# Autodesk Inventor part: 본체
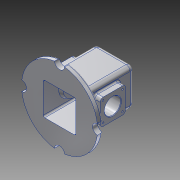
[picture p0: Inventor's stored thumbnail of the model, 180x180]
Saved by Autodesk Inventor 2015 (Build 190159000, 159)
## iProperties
Created: 2018-07
Part Number: 본체
Material: 알루미늄 6061
Document SubType Name: Modeling
Designer: pc
Density: 2.7 g/cm^3
Appearance: 알루미늄 - 평지
Mass: 909.432 g
Surface Area: 1017.53 cm^2
Volume: 336.827 cm^3
Author: pc
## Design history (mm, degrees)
sketch "스케치1"
  geometry: A1 r 10 centre (75, 0) between (74.333, 9.978) and (74.333, -9.978); A2 r 10 centre (0, -75) between (9.978, -74.333) and (-9.978, -74.333); A3 r 10 centre (0, 75) between (-9.978, 74.333) and (9.978, 74.333); A4 r 10 centre (-75, 0) between (-74.333, -9.978) and (-74.333, 9.978); A5 r 75 centre (0, 0) between (9.978, -74.333) and (74.333, -9.978); A6 r 75 centre (0, 0) between (74.333, 9.978) and (9.978, 74.333); A7 r 75 centre (0, 0) between (-9.978, 74.333) and (-74.333, 9.978); A8 r 75 centre (0, 0) between (-74.333, -9.978) and (-9.978, -74.333); 5 further points
  constraints: 16 point on circle, 8 centre point, 5 coincident, 2 horizontal alignment, 2 vertical alignment
  dimensions: "d1" = 20 diameter of A1; "d2" = 20 diameter of A2; "d3" = 20 diameter of A3; "d4" = 20 diameter of A4; "d5" = 75 radius of A5; "d6" = 75 radius of A6; "d7" = 75 radius of A7; "d8" = 75 radius of A8; "d9" = 150 distance of point (75, 0) point (-75, 0); "d10" = 150 distance of point (0, 75) point (0, -75); "d11" = 75 distance of point (0, 0) point (75, 0); "d12" = 75 distance of point (0, -75) point (0, 0)
extrude "돌출1" new body sketch "스케치1" distance "d13" = 10; taper "d14" = 0 deg
sketch "스케치2"
  geometry: L1 (-37, -37)-(37, -37); L2 (37, -37)-(37, 37); L3 (37, 37)-(-37, 37); L4 (-37, 37)-(-37, -37); L5 (0, -37)-(0, 37); L6 (37, 0)-(-37, 0); 2 further points
  constraints: 12 end point, 5 midpoint, 2 parallel, 1 coincident, 1 horizontal, 1 perpendicular
  dimensions: "d15" = 74 distance of L3.end L2.end; "d16" = 74 distance of L2.end L1.end
extrude "돌출2" join sketch "스케치2" distance "d17" = 100; taper "d18" = 0 deg
sketch "스케치3"
  geometry: L1 (-20, -20)-(20, -20); L2 (20, -20)-(20, 20); L3 (20, 20)-(-20, 20); L4 (-20, 20)-(-20, -20); L5 (0, -20)-(0, 20); L6 (20, 0)-(-20, 0); 1 further point
  constraints: 12 end point, 4 midpoint, 2 parallel, 1 horizontal, 1 perpendicular
  dimensions: "d19" = 40 distance of L3.end L2.end; "d20" = 40 distance of L2.end L1.end; "d21" = 20 distance of L6.end point (0, 0); "d22" = 20 distance of L5.end point (0, 0)
extrude "돌출3" join sketch "스케치3" distance "d23" = 7; taper "d24" = 0 deg
sketch "스케치4"
  geometry: L1 (-32, 32)-(32, 32); L2 (32, 32)-(32, -32); L3 (32, -32)-(-32, -32); L4 (-32, -32)-(-32, 32); L5 (-32, 0)-(32, 0); L6 (0, -32)-(0, 32); 2 further points
  constraints: 12 end point, 5 midpoint, 2 parallel, 1 coincident, 1 horizontal, 1 perpendicular
  dimensions: "d25" = 64 distance of L2.end L3.end; "d26" = 64 distance of L1.end L2.end
extrude "돌출4" cut sketch "스케치4" distance "d27" = 105; taper "d28" = 0 deg
node "작업 평면1"
sketch "스케치5"
  geometry: L1 (0, 0)-(55, 0); L2 (30, -25)-(80, -25); L3 (80, -25)-(80, 25); L4 (80, 25)-(30, 25); L5 (30, 25)-(30, -25); L6 (30, -25)-(80, 25); L7 (80, -25)-(30, 25)
  constraints: 14 end point, 2 horizontal, 2 midpoint, 2 parallel, 1 perpendicular
  dimensions: "d32" = 55 distance of L1.start L1.end; "d33" = 50 distance of L4.end L3.end; "d34" = 50 distance of L3.end L2.end
extrude "돌출5" join sketch "스케치5" stored distance "d35" = 105; taper "d36" = 0 deg
sketch "스케치6"
  geometry: L1 (0, 0)-(0, 55); C1 r 16 at (0, 55)
  constraints: 2 end point, 1 centre point, 1 coincident, 1 vertical
  dimensions: "d37" = 55 distance of L1.start L1.end; "d38" = 32 diameter of C1
extrude "돌출6" cut sketch "스케치6" stored distance "d39" = 105; taper "d40" = 0 deg
sketch "스케치7"
  geometry: L1 (-25, -30)-(-25, 25); C1 r 16 at (-25, 25)
  constraints: 2 end point, 1 centre point, 1 coincident, 1 vertical
  dimensions: "d41" = 55 distance of L1.start L1.end; "d42" = 32 diameter of C1
extrude "돌출7" cut sketch "스케치7" distance "d43" = 105; taper "d44" = 0 deg
sketch "스케치8"
  geometry: C1 r 17.5 at (0, 0); 1 further point
  constraints: 1 centre point, 1 coincident
  dimensions: "d45" = 35 diameter of C1
extrude "돌출8" join sketch "스케치8" distance "d46" = 3; taper "d47" = 0 deg
sketch "스케치9"
  geometry: C1 r 14 at (0, 0); 1 further point
  constraints: 1 centre point, 1 coincident
  dimensions: "d48" = 28 diameter of C1
extrude "돌출9" cut sketch "스케치9" distance "d49" = 4; taper "d50" = 0 deg
sketch "스케치10"
  geometry: C1 r 10.5 at (0, 0); 1 further point
  constraints: 1 centre point, 1 coincident
  dimensions: "d51" = 21 diameter of C1
extrude "돌출10" cut sketch "스케치10" stored distance "d52" = 4; taper "d53" = 0 deg
fillet "모깎기1" dims "d54" = 8
fillet "모깎기2" dims "d55" = 6
chamfer "모따기1" distance "d56" = 1; stored, may be unused: second distance "d57" = 2, angle "d58" = 45 deg
fillet "모깎기3" dims "d59" = 3
fillet "모깎기4" dims "d60" = 3
fillet "모깎기5" dims "d61" = 3
sketch "스케치11"
  geometry: A1 r 9 centre (-44, 38) between (-44, 47) and (-53, 38) reference; A2 r 9 centre (-6, 38) between (3, 38) and (-6, 47) reference; A3 r 9 centre (-6, 0) between (-6, -9) and (3, 0) reference; A4 r 9 centre (-44, 0) between (-53, 0) and (-44, -9) reference; 5 further points
  constraints: 4 coincident, 1 horizontal alignment
hole "구멍1" sketch "스케치11" at (-44, 38), (-6, 38), (-6, 0), (-44, 0) diameter "d62" = 3.242; stored, may be unused: countersink angle "d66" = 90 deg, drill point angle "d68" = 118 deg; dims "d63" = 8, "d64" = 4, "d65" = 2, "d67" = 10
fillet "모깎기6" dims "d69" = 3
sketch "스케치12"
  geometry: L1 (32, 55)-(25, 55); L2 (32, 80)-(25, 80); L3 (32, 80)-(25, 77.452); L4 (25, 77.452)-(25, 55); L5 (32, 80)-(32, 55); 1 further point
  constraints: 10 end point, 1 parallel
  dimensions: "d70" = 25 distance between parallel lines of L1 L2; "d82" = 7 horizontal distance of L2.start L3.end; "d85" = 22.45221 distance of L3.end L1.end; "d86" = 25 distance of L2.start L1.start; "d87" = 7 distance of L1.start L1.end; "d88" = 2.54779 distance of L3.end L2.end; "d89" = 80 distance from line of point (0, 0) L2; "d90" = 25 horizontal distance of point (0, 0) L1.end; "d91" = 55 vertical distance of L1.start point (0, 0)
revolve "회전1" sketch "스케치12" stored, may be unused: angle "d84" = 90 deg
sketch "스케치13"
  geometry: C1 r 25 at (0, 0) reference; C2 r 22.452 at (0, 0) reference; C3 r 16 at (0, 0); 1 further point
  constraints: 1 centre point, 1 coincident
  dimensions: "d92" = 32 diameter of C3
extrude "돌출11" cut sketch "스케치13" stored distance "d93" = 4; taper "d94" = 0 deg
node "작업 평면2"
sketch "스케치14"
  geometry: L1 (0, -9.978)-(0, 9.978) reference; L2 (-120, 17.5)-(-120, -17.5) reference; 3 further points
  constraints: 1 horizontal alignment, 1 midpoint, 1 other
  dimensions: "d96" = 30 distance from line of point (-90, 0) L2
feature "엠보싱1" sketch "스케치14" dims "d15" = 74, "d16" = 74, "d97" = 0.5, "d98" = 0
node "솔리드1"
mirror "대칭1"
mirror "대칭2"
mirror "대칭3"
node "투영된 루프1"
other parameters: "d95" = -37
